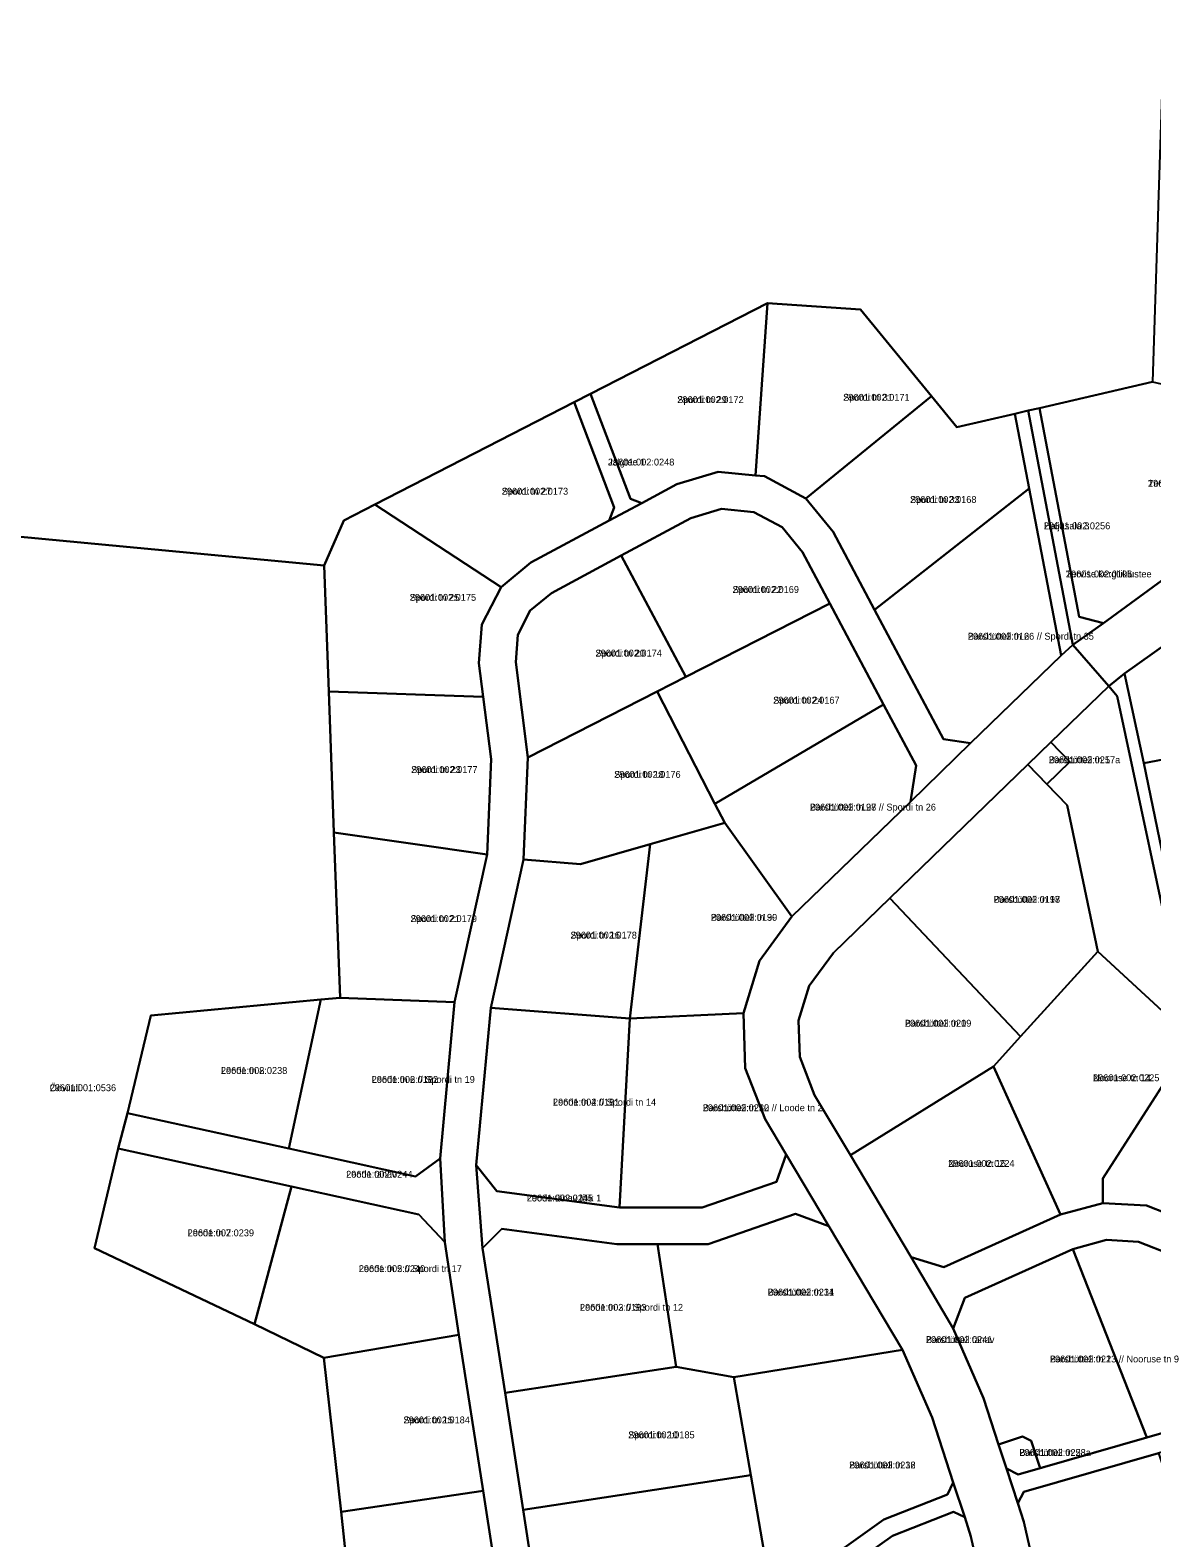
# Model space of a CAD drawing. Extents: x 518839 to 525192, y 6573164 to 6576561.
# Drawn here: x 522152.4 to 522397.5, y 6574633.7 to 6574963.2 of the extents above; entities that cross this region are included whole.
import ezdxf

# ---------------------------------------------------------------- set-up
doc = ezdxf.new("R2010")
doc.units = 0
for name, color, linetype in [('L_AADRESS', 7, 'Continuous'), ('PIIR', 7, 'Continuous'), ('TUNNUS', 7, 'Continuous')]:
    doc.layers.add(name, color=color, linetype=linetype)

msp = doc.modelspace()

# ---------------------------------------------------------------- linework, layer by layer
at = {"layer": 'PIIR'}
for points in [[(522558.33, 6574976.27), (522554.49, 6574943.99), (522524.42, 6574947.56), (522513.31, 6574948.88), (522495.14, 6574951.05), (522467.36, 6574954.37), (522436.45, 6574958.07), (522400.15, 6574962.4), (522398.94, 6574924.94), (522398.85, 6574922.42), (522397.69, 6574886.36), (522372.96, 6574880.62), (522370.52, 6574880.06), (522367.6, 6574879.38), (522354.95, 6574876.44), (522349.39, 6574883.21), (522333.86, 6574902.12), (522313.55, 6574903.56), (522274.91, 6574883.71), (522271.33, 6574881.87), (522227.77, 6574859.5), (522221, 6574856.02), (522216.66, 6574846.23), (522148.05, 6574852.71)], [(522256.08, 6574613.77), (522251.42, 6574643.94), (522246.14, 6574678.1), (522243.01, 6574698.34), (522242, 6574716.61), (522245.18, 6574750.79), (522252.3, 6574783.02), (522253.15, 6574803.9), (522251.43, 6574817.48), (522250.49, 6574824.88), (522251.12, 6574833.28), (522255.36, 6574841.48), (522261.84, 6574846.86), (522278.99, 6574856.06), (522286.07, 6574859.85), (522293.73, 6574863.96), (522302.74, 6574866.7), (522310.92, 6574865.89), (522312.91, 6574865.7), (522321.93, 6574860.87), (522327.89, 6574853.58), (522336.97, 6574836.54), (522352.02, 6574808.28), (522357.95, 6574807.35), (522344.8, 6574794.58), (522346.04, 6574802.48), (522338.93, 6574815.84), (522327.18, 6574837.9), (522321.2, 6574849.13), (522316.75, 6574854.57), (522310.54, 6574857.89), (522303.54, 6574858.58), (522296.81, 6574856.53), (522281.57, 6574848.36), (522266.33, 6574840.19), (522261.72, 6574836.37), (522258.98, 6574831.05), (522258.53, 6574825.09), (522261.17, 6574804.24), (522260.26, 6574781.98), (522253.1, 6574749.55), (522249.9, 6574715.13), (522251.31, 6574696.99), (522256.2, 6574665.39), (522260.15, 6574639.81), (522263.96, 6574615.16)], [(522148.05, 6574852.71), (522216.66, 6574846.23), (522217.7, 6574818.7), (522218.82, 6574787.83), (522220.15, 6574751.71), (522215.97, 6574751.39), (522178.81, 6574747.84), (522173.73, 6574726.48), (522171.64, 6574718.79), (522166.5, 6574697.03), (522201.42, 6574680.43), (522216.62, 6574673.07), (522220.41, 6574639.41), (522223.86, 6574606.37), (522224.31, 6574602.3), (522228.23, 6574566.69), (522194.89, 6574590.98), (522182.33, 6574598.84), (522162.84, 6574607.88), (522143.24, 6574617.06)], [(522404.18, 6574831.58), (522391.57, 6574822.57), (522388.11, 6574819.8), (522380.31, 6574828.88), (522387, 6574833.63), (522402.75, 6574845.12)], [(522364.35, 6574606.06), (522358.02, 6574634.03), (522356.65, 6574638.2), (522354.16, 6574645.81), (522349.51, 6574659.98), (522343.05, 6574674.81), (522326.95, 6574701.84), (522317.65, 6574717.45), (522313.04, 6574725.19), (522308.7, 6574736.37), (522308.28, 6574748.34), (522311.81, 6574759.8), (522318.9, 6574769.46), (522344.8, 6574794.58), (522357.95, 6574807.35), (522377.71, 6574826.51), (522380.31, 6574828.88), (522388.11, 6574819.8), (522375.44, 6574807.59), (522370.41, 6574802.71), (522340.27, 6574773.47), (522327.98, 6574761.54), (522322.68, 6574754.33), (522320.34, 6574746.75), (522320.62, 6574738.82), (522323.86, 6574730.47), (522331.66, 6574717.37), (522344.96, 6574695.06), (522354.11, 6574679.48), (522360.74, 6574664.25), (522364.06, 6574654.12), (522365.78, 6574648.89), (522368.27, 6574641.29), (522369.6, 6574637.23), (522375.42, 6574611.51)], [(522403.85, 6574752.49), (522389.99, 6574817.67), (522388.11, 6574819.8), (522391.57, 6574822.57), (522395.76, 6574803.01), (522401.2, 6574776.83)], [(522401.73, 6574695.62), (522394.63, 6574698.42), (522387.66, 6574698.81), (522380.3, 6574696.81), (522356.67, 6574686.13), (522354.11, 6574679.48), (522344.96, 6574695.06), (522352.07, 6574692.83), (522377.59, 6574704.37), (522386.82, 6574706.87), (522396.37, 6574706.34), (522405.26, 6574702.83)]]:
    msp.add_lwpolyline(points, dxfattribs=at)
for points in [[(522274.91, 6574883.71), (522313.55, 6574903.56), (522310.92, 6574865.89), (522302.74, 6574866.7), (522293.73, 6574863.96), (522286.07, 6574859.85), (522283.6, 6574860.78)], [(522313.55, 6574903.56), (522333.86, 6574902.12), (522349.39, 6574883.21), (522321.93, 6574860.87), (522312.91, 6574865.7), (522310.92, 6574865.89)], [(522372.96, 6574880.62), (522397.69, 6574886.36), (522418.62, 6574881.57), (522416.06, 6574872.54), (522420.43, 6574851.14), (522402.75, 6574845.12), (522387, 6574833.63), (522381.66, 6574835.01)], [(522271.33, 6574881.87), (522274.91, 6574883.71), (522283.6, 6574860.78), (522286.07, 6574859.85), (522278.99, 6574856.06), (522280.04, 6574858.87)], [(522321.93, 6574860.87), (522349.39, 6574883.21), (522354.95, 6574876.44), (522367.6, 6574879.38), (522370.72, 6574863.03), (522336.97, 6574836.54), (522327.89, 6574853.58)], [(522227.77, 6574859.5), (522271.33, 6574881.87), (522280.04, 6574858.87), (522278.99, 6574856.06), (522261.84, 6574846.86), (522255.36, 6574841.48)], [(522367.6, 6574879.38), (522370.52, 6574880.06), (522380.31, 6574828.88), (522377.71, 6574826.51), (522370.72, 6574863.03)], [(522370.52, 6574880.06), (522372.96, 6574880.62), (522381.66, 6574835.01), (522387, 6574833.63), (522380.31, 6574828.88)], [(522336.97, 6574836.54), (522370.72, 6574863.03), (522377.71, 6574826.51), (522357.95, 6574807.35), (522352.02, 6574808.28)], [(522221, 6574856.02), (522227.77, 6574859.5), (522255.36, 6574841.48), (522251.12, 6574833.28), (522250.49, 6574824.88), (522251.43, 6574817.48), (522217.7, 6574818.7), (522216.66, 6574846.23)], [(522281.57, 6574848.36), (522296.81, 6574856.53), (522303.54, 6574858.58), (522310.54, 6574857.89), (522316.75, 6574854.57), (522321.2, 6574849.13), (522327.18, 6574837.9), (522295.69, 6574821.84)], [(522261.72, 6574836.37), (522266.33, 6574840.19), (522281.57, 6574848.36), (522295.69, 6574821.84), (522289.43, 6574818.65), (522261.17, 6574804.24), (522258.53, 6574825.09), (522258.98, 6574831.05)], [(522391.57, 6574822.57), (522404.18, 6574831.58), (522422.93, 6574840.01), (522429.14, 6574809.32), (522395.76, 6574803.01)], [(522289.43, 6574818.65), (522295.69, 6574821.84), (522327.18, 6574837.9), (522338.93, 6574815.84), (522302.07, 6574794.14)], [(522375.44, 6574807.59), (522388.11, 6574819.8), (522389.99, 6574817.67), (522403.85, 6574752.49), (522405.28, 6574749.46), (522412.46, 6574743.59), (522486.41, 6574695.39), (522484.23, 6574692.04), (522455.26, 6574710.92), (522429.95, 6574727.42), (522406.42, 6574742.75), (522385.71, 6574761.84), (522379.04, 6574793.83), (522374.59, 6574798.41), (522379.62, 6574803.28)], [(522217.7, 6574818.7), (522251.43, 6574817.48), (522253.15, 6574803.9), (522252.3, 6574783.02), (522218.82, 6574787.83)], [(522261.17, 6574804.24), (522289.43, 6574818.65), (522302.07, 6574794.14), (522304.21, 6574789.98), (522287.92, 6574785.32), (522272.7, 6574780.96), (522260.26, 6574781.98)], [(522302.07, 6574794.14), (522338.93, 6574815.84), (522346.04, 6574802.48), (522344.8, 6574794.58), (522318.9, 6574769.46), (522304.21, 6574789.98)], [(522370.41, 6574802.71), (522375.44, 6574807.59), (522379.62, 6574803.28), (522374.59, 6574798.41)], [(522395.76, 6574803.01), (522429.14, 6574809.32), (522434.49, 6574783.12), (522401.2, 6574776.83)], [(522340.27, 6574773.47), (522370.41, 6574802.71), (522374.59, 6574798.41), (522379.04, 6574793.83), (522385.71, 6574761.84), (522368.87, 6574743.25)], [(522287.92, 6574785.32), (522304.21, 6574789.98), (522318.9, 6574769.46), (522311.81, 6574759.8), (522308.28, 6574748.34), (522283.45, 6574747.2)], [(522218.82, 6574787.83), (522252.3, 6574783.02), (522245.18, 6574750.79), (522220.15, 6574751.71)], [(522260.26, 6574781.98), (522272.7, 6574780.96), (522287.92, 6574785.32), (522283.45, 6574747.2), (522253.1, 6574749.55)], [(522327.98, 6574761.54), (522340.27, 6574773.47), (522368.87, 6574743.25), (522362.95, 6574736.73), (522331.66, 6574717.37), (522323.86, 6574730.47), (522320.62, 6574738.82), (522320.34, 6574746.75), (522322.68, 6574754.33)], [(522385.71, 6574761.84), (522406.42, 6574742.75), (522386.82, 6574712.23), (522386.82, 6574706.87), (522377.59, 6574704.37), (522362.95, 6574736.73), (522368.87, 6574743.25)], [(522178.81, 6574747.84), (522215.97, 6574751.39), (522208.97, 6574718.79), (522173.73, 6574726.48)], [(522215.97, 6574751.39), (522220.15, 6574751.71), (522245.18, 6574750.79), (522242, 6574716.61), (522236.66, 6574712.7), (522208.97, 6574718.79)], [(522253.1, 6574749.55), (522283.45, 6574747.2), (522281.18, 6574705.91), (522254.39, 6574709.49), (522249.9, 6574715.13)], [(522283.45, 6574747.2), (522308.28, 6574748.34), (522308.7, 6574736.37), (522313.04, 6574725.19), (522317.65, 6574717.45), (522315.49, 6574711.52), (522299.26, 6574705.91), (522281.18, 6574705.91)], [(522406.42, 6574742.75), (522429.95, 6574727.42), (522411.01, 6574699.42), (522405.26, 6574702.83), (522396.37, 6574706.34), (522386.82, 6574706.87), (522386.82, 6574712.23)], [(522331.66, 6574717.37), (522362.95, 6574736.73), (522377.59, 6574704.37), (522352.07, 6574692.83), (522344.96, 6574695.06)], [(522173.73, 6574726.48), (522208.97, 6574718.79), (522236.66, 6574712.7), (522242, 6574716.61), (522243.01, 6574698.34), (522237.36, 6574704.36), (522209.52, 6574710.48), (522171.64, 6574718.79)], [(522171.64, 6574718.79), (522209.52, 6574710.48), (522201.42, 6574680.43), (522166.5, 6574697.03)], [(522249.9, 6574715.13), (522254.39, 6574709.49), (522281.18, 6574705.91), (522299.26, 6574705.91), (522315.49, 6574711.52), (522317.65, 6574717.45), (522326.95, 6574701.84), (522319.67, 6574704.5), (522300.6, 6574697.91), (522289.5, 6574697.91), (522280.65, 6574697.91), (522255.51, 6574701.27), (522251.31, 6574696.99)], [(522209.52, 6574710.48), (522237.36, 6574704.36), (522243.01, 6574698.34), (522246.14, 6574678.1), (522216.62, 6574673.07), (522201.42, 6574680.43)], [(522289.5, 6574697.91), (522300.6, 6574697.91), (522319.67, 6574704.5), (522326.95, 6574701.84), (522343.05, 6574674.81), (522306.22, 6574668.8), (522293.6, 6574671.1)], [(522255.51, 6574701.27), (522280.65, 6574697.91), (522289.5, 6574697.91), (522293.6, 6574671.1), (522256.2, 6574665.39), (522251.31, 6574696.99)], [(522380.3, 6574696.81), (522387.66, 6574698.81), (522394.63, 6574698.42), (522401.73, 6574695.62), (522417.43, 6574686.3), (522422.47, 6574681.95), (522425.69, 6574676.12), (522428.79, 6574666.98), (522427.51, 6574664.53), (522396.43, 6574655.61)], [(522356.67, 6574686.13), (522380.3, 6574696.81), (522396.43, 6574655.61), (522373.13, 6574648.93), (522371.18, 6574654.87), (522369.29, 6574655.83), (522364.06, 6574654.12), (522360.74, 6574664.25), (522354.11, 6574679.48)], [(522216.62, 6574673.07), (522246.14, 6574678.1), (522251.42, 6574643.94), (522220.41, 6574639.41)], [(522306.22, 6574668.8), (522343.05, 6574674.81), (522349.51, 6574659.98), (522354.16, 6574645.81), (522352.92, 6574643.18), (522338.98, 6574637.69), (522327.75, 6574629.72), (522314.16, 6574622.93), (522309.92, 6574647.41)], [(522256.2, 6574665.39), (522293.6, 6574671.1), (522306.22, 6574668.8), (522309.92, 6574647.41), (522260.15, 6574639.81)], [(522365.78, 6574648.89), (522368.32, 6574647.54), (522396.43, 6574655.61), (522427.51, 6574664.53), (522428.79, 6574666.98), (522431.37, 6574659.4), (522428.8, 6574660.74), (522398.97, 6574652.18), (522369.57, 6574643.74), (522368.27, 6574641.29)], [(522364.06, 6574654.12), (522369.29, 6574655.83), (522371.18, 6574654.87), (522373.13, 6574648.93), (522368.32, 6574647.54), (522365.78, 6574648.89)], [(522369.57, 6574643.74), (522398.97, 6574652.18), (522409.11, 6574622.32), (522375.42, 6574611.51), (522369.6, 6574637.23), (522368.27, 6574641.29)], [(522260.15, 6574639.81), (522309.92, 6574647.41), (522314.16, 6574622.93), (522295.21, 6574617.91), (522266.24, 6574613.49), (522263.96, 6574615.16)], [(522263.96, 6574615.16), (522266.24, 6574613.49), (522295.21, 6574617.91), (522314.16, 6574622.93), (522327.75, 6574629.72), (522338.98, 6574637.69), (522352.92, 6574643.18), (522354.16, 6574645.81), (522356.65, 6574638.2), (522354.17, 6574639.37), (522340.89, 6574634.15), (522329.81, 6574626.28), (522322.71, 6574622.73), (522315.58, 6574619.16), (522296.03, 6574613.98), (522266.85, 6574609.53), (522265.18, 6574607.25)], [(522220.41, 6574639.41), (522251.42, 6574643.94), (522256.08, 6574613.77), (522254.41, 6574611.46), (522223.86, 6574606.37)], [(522322.71, 6574622.73), (522329.81, 6574626.28), (522340.89, 6574634.15), (522354.17, 6574639.37), (522356.65, 6574638.2), (522358.02, 6574634.03), (522364.35, 6574606.06), (522327.6, 6574598.37)]]:
    msp.add_lwpolyline(points, close=True, dxfattribs=at)

# ---------------------------------------------------------------- texts
at = {"layer": 'L_AADRESS'}
for s, p in [('Spordi tn 29', (522293.85, 6574881.71)), ('Spordi tn 31', (522330.11, 6574882.21)), ('Jalgtee 1', (522278.7, 6574868.06)), ('Spordi tn 27', (522255.49, 6574861.68)), ('Tervise tn 25', (522396.7, 6574863.42)), ('Spordi tn 33', (522344.72, 6574859.88)), ('Haljasala 3', (522373.96, 6574854.12)), ('Tervise kergliiklustee', (522378.76, 6574843.6)), ('Spordi tn 25', (522235.38, 6574838.49)), ('Spordi tn 22', (522305.93, 6574840.21)), ('Barsbütteli tn 26 // Spordi tn 35', (522357.34, 6574829.99)), ('Spordi tn 20', (522275.97, 6574826.3)), ('Spordi tn 24', (522314.81, 6574816.02)), ('Barsbütteli tn 17a', (522375.02, 6574803)), ('Spordi tn 23', (522235.69, 6574800.86)), ('Spordi tn 18', (522280.07, 6574799.8)), ('Barsbütteli tn 28 // Spordi tn 26', (522322.82, 6574792.65)), ('Barsbütteli tn 17', (522362.99, 6574772.49)), ('Barsbütteli tn 30', (522301.18, 6574768.56)), ('Spordi tn 21', (522235.56, 6574768.28)), ('Spordi tn 16', (522270.51, 6574764.67)), ('Barsbütteli tn 19', (522343.6, 6574745.42)), ('Loode tn 8', (522194.12, 6574735.09)), ('Loode tn 6 // Spordi tn 19', (522227.07, 6574733.13)), ('Nooruse tn 14', (522384.69, 6574733.5)), ('Ööviiuli', (522156.71, 6574731.32)), ('Loode tn 4 // Spordi tn 14', (522266.68, 6574728.17)), ('Barsbütteli tn 32 // Loode tn 2', (522299.41, 6574726.95)), ('Loode tänav', (522221.48, 6574712.41)), ('Nooruse tn 16', (522353.04, 6574714.78)), ('Loode tänav lõik 1', (522260.95, 6574707.22)), ('Loode tn 7', (522186.85, 6574699.61)), ('Loode tn 5 // Spordi tn 17', (522224.25, 6574691.78)), ('Barsbütteli tn 34', (522313.61, 6574686.65)), ('Loode tn 3 // Spordi tn 12', (522272.58, 6574683.33)), ('Barsbütteli tänav', (522348.2, 6574676.28)), ('Barsbütteli tn 23 // Nooruse tn 9', (522375.27, 6574672.04)), ('Spordi tn 15', (522234.02, 6574658.72)), ('Spordi tn 10', (522283.13, 6574655.46)), ('Barsbütteli tn 23a', (522368.6, 6574651.61)), ('Barsbütteli tn 36', (522331.41, 6574648.87))]:
    msp.add_text(s, height=1.5, dxfattribs=at).set_placement(p)
at = {"layer": 'TUNNUS'}
for s, p in [('29601:002:0172', (522293.85, 6574881.71)), ('29601:002:0171', (522330.11, 6574882.21)), ('29601:002:0248', (522278.7, 6574868.06)), ('29601:002:0173', (522255.49, 6574861.68)), ('29601:002:0064', (522396.7, 6574863.42)), ('29601:002:0168', (522344.72, 6574859.88)), ('29601:002:0256', (522373.96, 6574854.12)), ('29601:002:0106', (522378.76, 6574843.6)), ('29601:002:0175', (522235.38, 6574838.49)), ('29601:002:0169', (522305.93, 6574840.21)), ('29601:002:0166', (522357.34, 6574829.99)), ('29601:002:0174', (522275.97, 6574826.3)), ('29601:002:0167', (522314.81, 6574816.02)), ('29601:002:0257', (522375.02, 6574803)), ('29601:002:0177', (522235.69, 6574800.86)), ('29601:002:0176', (522280.07, 6574799.8)), ('29601:002:0197', (522322.82, 6574792.65)), ('29601:002:0198', (522362.99, 6574772.49)), ('29601:002:0199', (522301.18, 6574768.56)), ('29601:002:0179', (522235.56, 6574768.28)), ('29601:002:0178', (522270.51, 6574764.67)), ('29601:002:0209', (522343.6, 6574745.42)), ('29601:002:0238', (522194.12, 6574735.09)), ('29601:002:0182', (522227.07, 6574733.13)), ('29601:002:0225', (522384.69, 6574733.5)), ('29601:001:0536', (522156.71, 6574731.32)), ('29601:002:0181', (522266.68, 6574728.17)), ('29601:002:0210', (522299.41, 6574726.95)), ('29601:002:0224', (522353.04, 6574714.78)), ('29601:002:0244', (522221.48, 6574712.41)), ('29601:002:0245', (522260.95, 6574707.22)), ('29601:002:0239', (522186.85, 6574699.61)), ('29601:002:0240', (522224.25, 6574691.78)), ('29601:002:0211', (522313.61, 6574686.65)), ('29601:002:0183', (522272.58, 6574683.33)), ('29601:002:0241', (522348.2, 6574676.28)), ('29601:002:0213', (522375.27, 6574672.04)), ('29601:002:0184', (522234.02, 6574658.72)), ('29601:002:0185', (522283.13, 6574655.46)), ('29601:002:0258', (522368.6, 6574651.61)), ('29601:002:0212', (522331.41, 6574648.87))]:
    msp.add_text(s, height=1.5, dxfattribs=at).set_placement(p)

doc.saveas('drawing.dxf')
